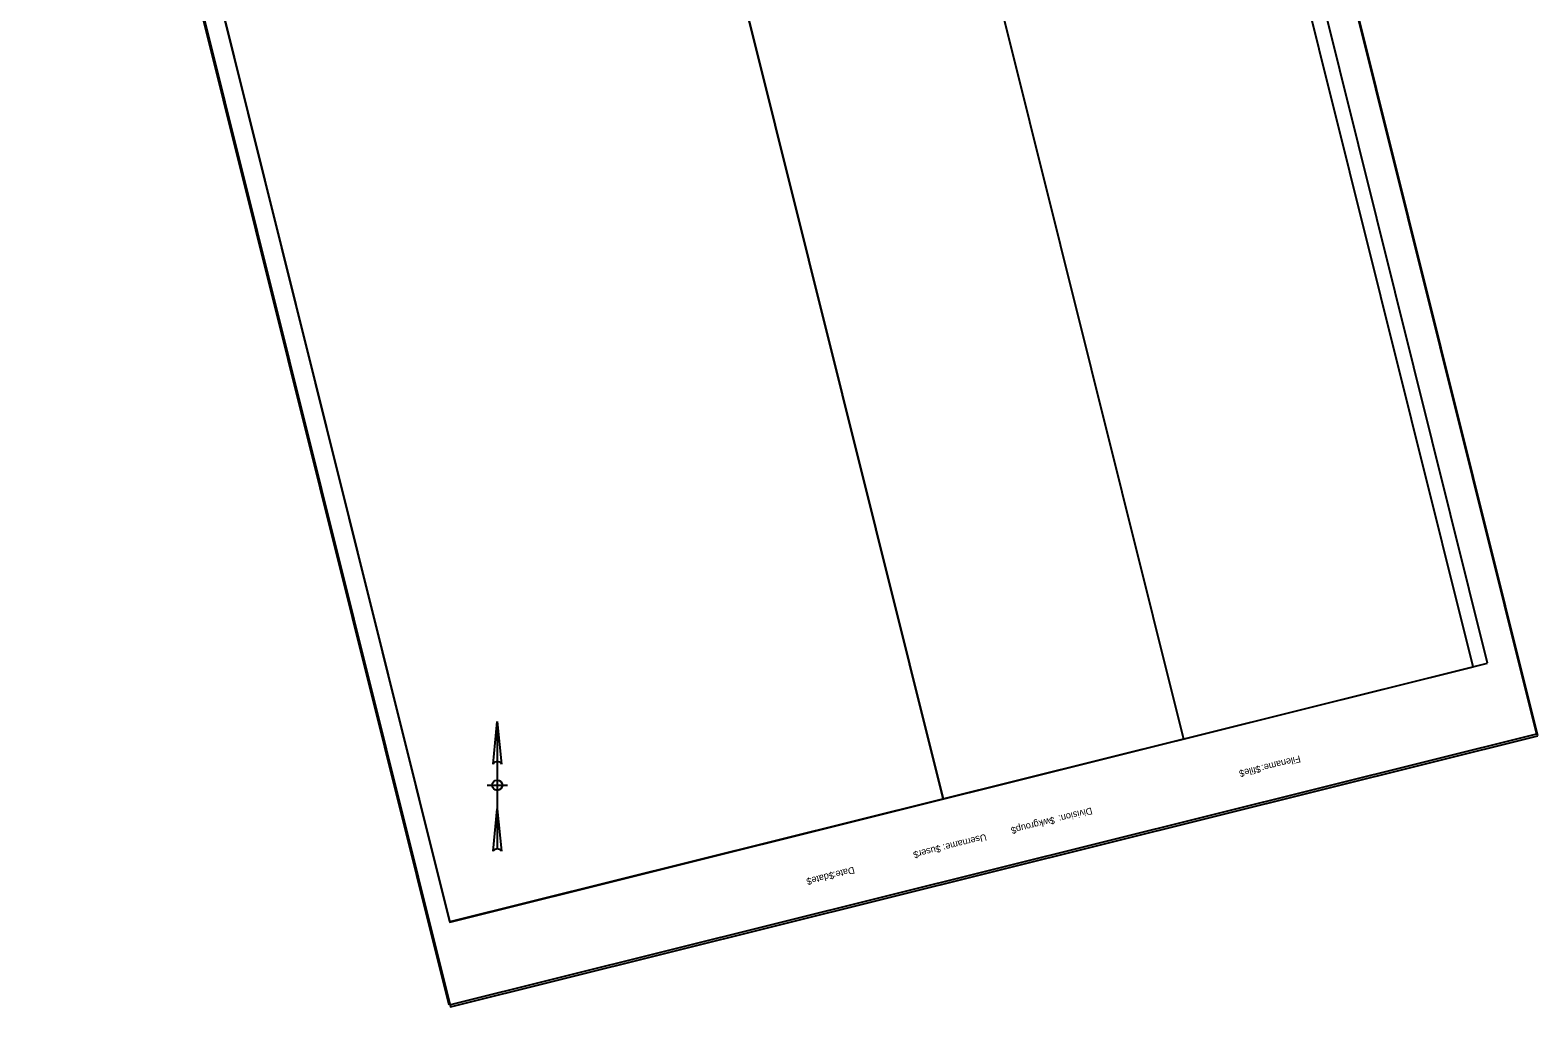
# Model space of a CAD drawing. Extents: x 1037414 to 1038154, y 780984 to 781943.
# Drawn here: x 1037414 to 1038154, y 780984 to 781464 of the extents above; entities that cross this region are included whole.
import ezdxf

# ---------------------------------------------------------------- set-up
doc = ezdxf.new("R2010")
doc.units = 0
for name, color, linetype in [('CLIPS', 7, 'Continuous'), ('Default', 7, 'Continuous'), ('PLOT BOUNDARY', 7, 'Continuous')]:
    doc.layers.add(name, color=color, linetype=linetype)

msp = doc.modelspace()

# ---------------------------------------------------------------- linework, layer by layer
at = {"layer": 'CLIPS'}
for points in [[(1038122.09, 781151.18), (1037940.65, 781878.9), (1037680.61, 781814.07), (1037862.05, 781086.35)], [(1037619.87, 781025.99), (1037438.46, 781753.58), (1037798.58, 781843.37), (1037979.99, 781115.77)], [(1037862.05, 781086.35), (1037680.61, 781814.07), (1037438.41, 781753.68), (1037619.85, 781025.96)]]:
    msp.add_lwpolyline(points, close=True, dxfattribs=at)
at = {"layer": 'Default'}
for p, q in [((1038129.26, 781152.97), (1037935.72, 781929.2)), ((1037426.32, 781802.2), (1037619.85, 781025.96)), ((1037619.85, 781025.96), (1038129.26, 781152.97)), ((1037641.08, 781103.51), (1037643.17, 781124.34)), ((1037643.17, 781124.34), (1037643.17, 781061.84)), ((1037643.17, 781124.34), (1037645.25, 781103.51)), ((1037638.17, 781093.09), (1037648.17, 781093.09)), ((1037641.08, 781060.73), (1037643.17, 781081.56)), ((1037643.17, 781081.56), (1037645.25, 781060.73))]:
    msp.add_line(p, q, dxfattribs=at)
msp.add_lwpolyline([(1038153.89, 781117.4), (1037948.26, 781942.15), (1037414.59, 781809.1), (1037620.23, 780984.35)], close=True, dxfattribs=at)
msp.add_circle((1037643.17, 781093.09), 2.5, dxfattribs=at)
for centre in [(1037643.17, 781102.13), (1037643.17, 781059.34)]:
    msp.add_arc(centre, 2.5, 33.55731, 146.44269, dxfattribs=at)
at = {"layer": 'PLOT BOUNDARY'}
msp.add_lwpolyline([(1037619.54, 780985.1), (1037413.91, 781809.85), (1037947.57, 781942.9), (1038153.2, 781118.15)], close=True, dxfattribs=at)

# ---------------------------------------------------------------- texts
at = {"layer": 'Default'}
for s, p in [('Filename:', (1038036.97, 781107.72)), ('$file$', (1038017.43, 781102.85)), ('Division:', (1037934.76, 781082.24)), ('$wkgroup$', (1037916.31, 781077.64)), ('Username:', (1037882.84, 781069.29)), ('$user$', (1037860.41, 781063.7)), ('Date:', (1037818.08, 781053.15)), ('$date$', (1037807.95, 781050.62))]:
    msp.add_text(s, height=3.348, rotation=194, dxfattribs=at).set_placement(p)

doc.saveas('drawing.dxf')
